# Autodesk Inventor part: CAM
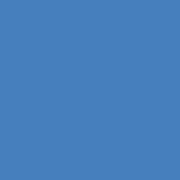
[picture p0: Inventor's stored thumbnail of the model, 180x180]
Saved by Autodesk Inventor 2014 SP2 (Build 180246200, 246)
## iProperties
Created: 2005-05
Part Number: CAM
Document SubType Name: Modeling
Designer: Administrator
Material: Allgemein
Density: 1 g/cm^3
Appearance: Vorgabe
Author: Administrator
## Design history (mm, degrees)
node "Volumenkörper"
node "Flächenkörper"
